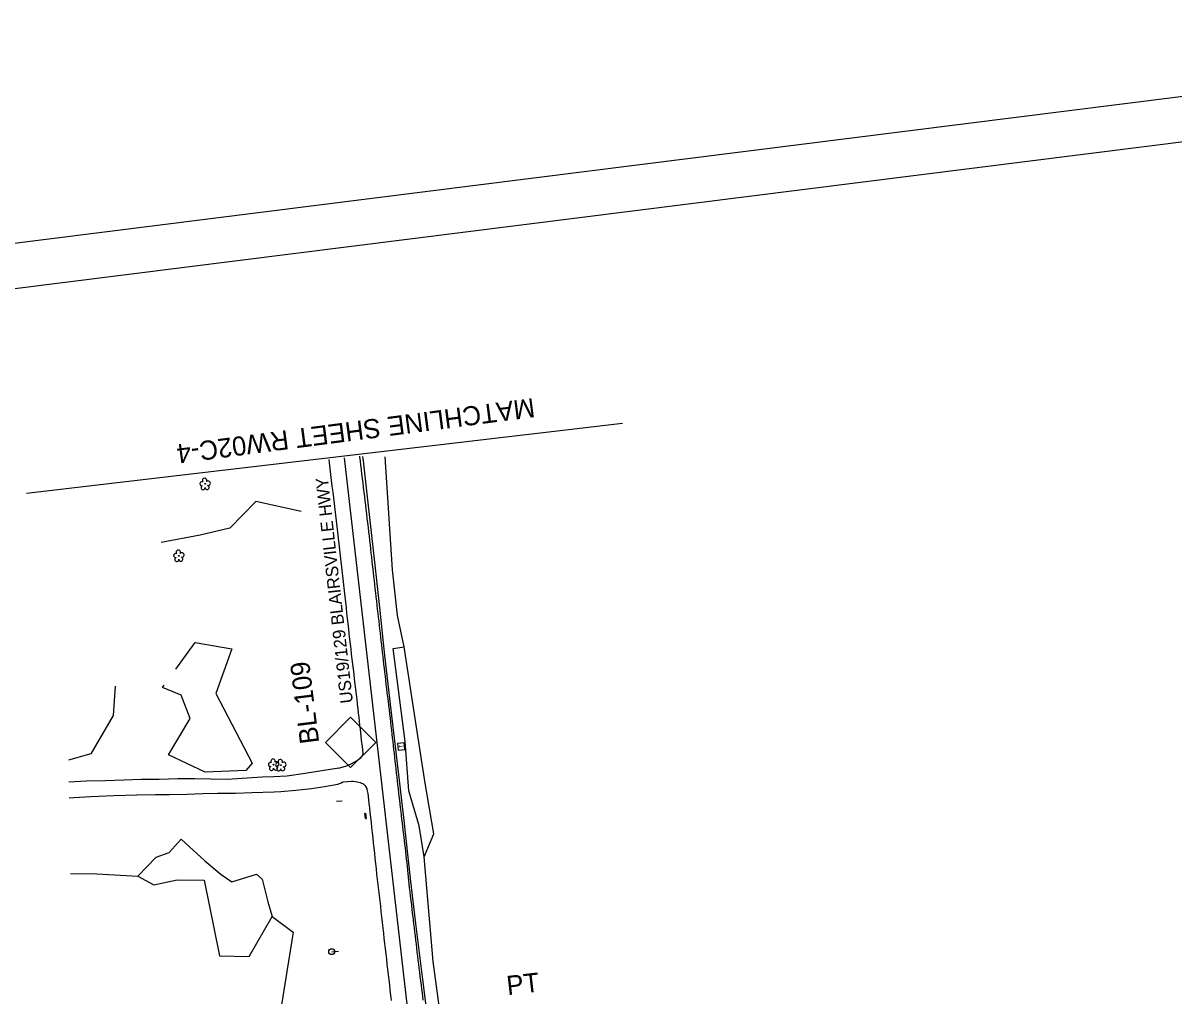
# Model space of a CAD drawing. Extents: x 477009 to 479892, y 492858 to 496862.
# Drawn here: x 477973 to 478933, y 496051 to 496862 of the extents above; entities that cross this region are included whole.
import ezdxf

# ---------------------------------------------------------------- set-up
doc = ezdxf.new("R2010")
doc.units = 0
for name, color, linetype in [('CTL Secondary Horizontal and Vertical CELL', 7, 'Continuous'), ('CTL Secondary Horizontal and Vertical Text', 7, 'Continuous'), ('CTL Sheet Border CELL', 7, 'Continuous'), ('Exist Guardrail', 7, 'Continuous'), ('Exist Horizontal Alignment', 7, 'Continuous'), ('Exist Other Culture Sign', 7, 'Continuous'), ('Exist Roads EOP', 7, 'Continuous'), ('Exist Roads EOP Text', 7, 'Continuous'), ('Exist Structure Minor Head and End Wall', 7, 'Continuous'), ('Exist Utilities Power Pole CELL', 7, 'Continuous'), ('Exist Utilities Telephone Pedestal CELL', 7, 'Continuous'), ('Exist Vegetation Hedge Row', 7, 'Continuous'), ('Exist Vegetation Tree CELL', 7, 'Continuous'), ('Exist Vegetation Woods Line', 7, 'Continuous'), ('Matchline', 7, 'Continuous'), ('Matchline Text', 7, 'Continuous'), ('Sheet Plot Border Outside CELL', 7, 'Continuous')]:
    doc.layers.add(name, color=color, linetype=linetype)

msp = doc.modelspace()

# ---------------------------------------------------------------- linework, layer by layer
at = {"layer": 'CTL Secondary Horizontal and Vertical CELL'}
msp.add_line((478246.12, 496262.13), (478246.12, 496262.13), dxfattribs=at)
msp.add_lwpolyline([(478225.26, 496262.2), (478246.23, 496283.17), (478267.23, 496262.17), (478246.26, 496241.2)], close=True, dxfattribs=at)
at = {"layer": 'CTL Sheet Border CELL'}
msp.add_lwpolyline([(477068.94, 496527.38), (477483.72, 493231.36), (479790.91, 493521.7), (479376.13, 496817.73)], close=True, dxfattribs=at)
at = {"layer": 'Exist Guardrail'}
for points in [[(478256.28, 496500.58), (478256.65, 496497), (478260.06, 496466.83), (478265.67, 496417.48), (478270.32, 496374.68), (478274.6, 496334.65), (478279.87, 496289.32), (478285.61, 496239.91), (478290.24, 496199.44), (478296.25, 496146.09)], [(478296.25, 496146.09), (478300.41, 496111.06), (478306.15, 496064.49), (478311.22, 496024.56), (478316.39, 495985.44), (478319.3, 495964.86), (478322.01, 495945.56)]]:
    msp.add_lwpolyline(points, dxfattribs=at)
at = {"layer": 'Exist Horizontal Alignment'}
msp.add_line((478294.37, 496036.52), (478241.07, 496499.45), dxfattribs=at)
at = {"layer": 'Exist Other Culture Sign'}
msp.add_line((478239.25, 496213.02), (478234.56, 496212.82), dxfattribs=at)
at = {"layer": 'Exist Roads EOP'}
for points in [[(478236.44, 496240.8), (478241.02, 496241.98), (478242.19, 496242.4), (478246.87, 496244.28), (478251.67, 496247.04), (478253.48, 496248.33), (478254.7, 496249.35), (478255.1, 496249.74), (478255.64, 496250.39), (478256.11, 496251.04), (478256.31, 496251.4), (478256.46, 496251.79), (478256.58, 496252.22), (478256.65, 496252.68), (478256.67, 496253.18), (478256.11, 496258.57), (478255.5, 496264), (478255.16, 496267), (478254.8, 496270.1), (478254.43, 496273.31), (478254.05, 496276.59), (478253.67, 496279.91), (478253.29, 496283.26), (478252.91, 496286.65), (478252.51, 496290.17), (478252.09, 496293.91), (478251.63, 496297.88), (478251.14, 496302.08), (478250.64, 496306.37), (478250.14, 496310.63), (478249.63, 496314.85), (478249.12, 496319.04), (478248.62, 496323.21), (478248.12, 496327.38), (478247.62, 496331.54), (478247.13, 496335.7), (478246.64, 496339.87), (478246.16, 496344.07), (478245.67, 496348.29), (478245.19, 496352.54), (478244.71, 496356.82), (478244.22, 496361.13), (478243.73, 496365.48), (478243.24, 496369.86), (478242.74, 496374.33), (478242.22, 496378.95), (478241.69, 496383.71), (478241.14, 496388.6), (478240.59, 496393.56), (478240.04, 496398.46), (478239.49, 496403.33), (478238.94, 496408.16), (478238.39, 496412.98), (478237.84, 496417.83), (478237.3, 496422.7), (478236.76, 496427.61), (478236.22, 496432.51), (478235.67, 496437.36), (478235.13, 496442.16), (478234.59, 496446.92), (478234.03, 496451.67), (478233.46, 496456.45), (478232.88, 496461.26), (478232.27, 496466.1), (478231.66, 496470.94), (478231.05, 496475.79), (478230.44, 496480.63), (478229.83, 496485.46), (478229.21, 496490.35), (478228.59, 496495.37), (478228.28, 496497.98)], [(478253.7, 496500.95), (478253.77, 496500.32), (478254.2, 496496.76), (478254.63, 496493.2), (478255.06, 496489.63), (478255.49, 496486.02), (478255.93, 496482.33), (478256.38, 496478.58), (478256.84, 496474.76), (478257.3, 496470.94), (478257.74, 496467.18), (478258.18, 496463.49), (478258.61, 496459.87), (478259.04, 496456.26), (478259.47, 496452.61), (478259.92, 496448.92), (478260.38, 496445.2), (478260.84, 496441.47), (478261.28, 496437.77), (478261.7, 496434.11), (478262.11, 496430.48), (478262.51, 496426.9), (478262.89, 496423.4), (478263.26, 496419.96), (478263.62, 496416.6), (478263.97, 496413.3), (478264.33, 496410.05), (478264.69, 496406.85), (478265.05, 496403.7), (478265.42, 496400.52), (478265.8, 496397.24), (478266.19, 496393.86), (478266.58, 496390.37), (478266.98, 496386.85), (478267.37, 496383.39), (478267.76, 496380), (478268.15, 496376.66), (478268.54, 496373.33), (478268.93, 496369.98), (478269.31, 496366.6), (478269.7, 496363.2), (478270.08, 496359.81), (478270.46, 496356.49), (478270.84, 496353.23), (478271.22, 496350.03), (478271.59, 496346.86), (478271.96, 496343.64), (478272.33, 496340.4), (478272.7, 496337.12), (478273.07, 496333.82), (478273.44, 496330.53), (478273.82, 496327.24), (478274.21, 496323.95), (478274.6, 496320.65), (478274.99, 496317.31), (478275.39, 496313.93), (478275.79, 496310.52), (478276.2, 496307.07), (478276.62, 496303.58), (478277.04, 496300.04), (478277.47, 496296.46), (478277.9, 496292.88), (478278.32, 496289.34), (478278.74, 496285.86), (478279.15, 496282.42), (478279.55, 496279.02), (478279.93, 496275.67), (478280.31, 496272.37), (478280.67, 496269.1), (478281.03, 496265.86), (478281.39, 496262.62), (478281.75, 496259.37), (478282.11, 496256.12), (478282.47, 496252.86), (478282.84, 496249.61), (478283.21, 496246.36), (478283.59, 496243.1), (478283.96, 496239.84), (478284.33, 496236.56), (478284.71, 496233.26), (478285.08, 496229.94), (478285.45, 496226.64), (478285.82, 496223.41), (478286.2, 496220.25), (478286.57, 496217.14), (478286.95, 496214.06), (478287.32, 496210.92), (478287.7, 496207.75), (478288.09, 496204.54), (478288.47, 496201.32), (478288.85, 496198.16), (478289.22, 496195.04), (478289.59, 496191.97), (478289.95, 496188.95), (478290.64, 496183.01), (478291.31, 496177.17), (478291.66, 496174.16), (478292.01, 496171.07), (478292.38, 496167.91), (478292.74, 496164.74), (478293.08, 496161.62), (478293.4, 496158.56), (478293.7, 496155.55), (478294.28, 496149.64), (478294.88, 496143.85), (478295.21, 496140.86), (478295.58, 496137.62), (478295.99, 496134.13), (478296.44, 496130.39), (478296.91, 496126.64), (478297.34, 496123.13), (478297.74, 496119.86), (478298.11, 496116.83), (478298.48, 496113.85), (478298.85, 496110.74), (478299.23, 496107.51), (478299.62, 496104.15), (478300.01, 496100.74), (478300.4, 496097.35), (478300.8, 496093.98), (478301.2, 496090.64), (478301.6, 496087.32), (478301.99, 496083.99), (478302.39, 496080.66), (478302.79, 496077.33), (478303.2, 496073.97), (478303.63, 496070.52), (478304.08, 496066.99), (478304.55, 496063.37), (478305.01, 496059.81), (478305.44, 496056.43), (478305.83, 496053.24), (478306.54, 496047.29)], [(478236.44, 496240.8), (478223.92, 496238.63), (478208.46, 496236.09), (478193.22, 496234.13), (478182.34, 496233.34), (478172.59, 496233.07), (478156, 496231.93), (478143.27, 496231.15), (478129.63, 496231.57), (478116.33, 496231.74), (478102.38, 496231.66), (478086.58, 496231.11), (478071.99, 496231.1), (478057.25, 496230.71), (478041.97, 496230.07), (478025.75, 496229.73), (478011.4, 496229.02)], [(478280.38, 496047.01), (478279.88, 496051.32), (478279.39, 496055.63), (478278.89, 496059.93), (478278.38, 496064.23), (478277.88, 496068.53), (478277.37, 496072.82), (478276.86, 496077.12), (478276.35, 496081.41), (478275.84, 496085.72), (478275.34, 496090.04), (478274.86, 496094.39), (478274.38, 496098.76), (478273.9, 496103.16), (478273.41, 496107.59), (478272.91, 496112.07), (478272.39, 496116.58), (478271.87, 496121.09), (478271.35, 496125.59), (478270.82, 496130.08), (478270.28, 496134.54), (478269.74, 496138.99), (478269.23, 496143.42), (478268.72, 496147.85), (478268.24, 496152.27), (478267.76, 496156.67), (478267.29, 496161.04), (478266.83, 496165.38), (478266.37, 496169.69), (478265.91, 496173.99), (478265.45, 496178.28), (478264.98, 496182.58), (478264.52, 496186.88), (478264.06, 496191.15), (478263.59, 496195.36), (478263.13, 496199.52), (478262.67, 496203.62), (478262.23, 496207.52), (478261.83, 496211.07), (478261.45, 496214.26), (478260.8, 496219.52), (478260.23, 496222.78), (478259.97, 496223.62), (478259.49, 496224.64), (478259.08, 496225.35), (478258.86, 496225.63), (478258.25, 496226.26), (478257.44, 496226.93), (478256.61, 496227.5), (478255.74, 496227.96), (478254.65, 496228.37), (478251.74, 496229.08), (478248.34, 496229.51), (478246.76, 496229.53), (478243.69, 496229.29), (478240.19, 496228.9), (478238.79, 496228.7)], [(478011.65, 496215.98), (478015.46, 496216.17), (478029.85, 496217.03), (478048.94, 496217.92), (478068.01, 496218.49), (478083.78, 496218.75), (478095.26, 496218.68), (478109.93, 496219.12), (478122.87, 496219.43), (478135.39, 496219.7), (478150.29, 496219.81), (478164.07, 496220.51), (478182.61, 496220.86), (478188.19, 496221.11), (478200.59, 496222.22), (478213.8, 496223.77), (478224.41, 496225.3), (478235.71, 496227.33), (478240.19, 496228.9)]]:
    msp.add_lwpolyline(points, dxfattribs=at)
at = {"layer": 'Exist Structure Minor Head and End Wall'}
for p, q in [((478258.16, 496203), (478258.99, 496203.1)), ((478258.66, 496198.6), (478258.16, 496203)), ((478259.48, 496198.7), (478258.99, 496203.1)), ((478258.66, 496198.6), (478259.48, 496198.7))]:
    msp.add_line(p, q, dxfattribs=at)
at = {"layer": 'Exist Utilities Power Pole CELL'}
for q in [(478236.14, 496088.04), (478230.53, 496087.63)]:
    msp.add_line((478230.53, 496087.63), q, dxfattribs=at)
msp.add_circle((478230.53, 496087.63), 2.45, dxfattribs=at)
at = {"layer": 'Exist Utilities Telephone Pedestal CELL'}
msp.add_line((478288.46, 496258.61), (478288.46, 496258.61), dxfattribs=at)
msp.add_lwpolyline([(478291.57, 496256.22), (478290.95, 496261.77), (478285.39, 496261.15), (478286.01, 496255.59), (478291.57, 496256.22)], dxfattribs=at)
at = {"layer": 'Exist Vegetation Hedge Row'}
for points in [[(478205.09, 496454.64), (478167.18, 496462.99), (478145.75, 496440.73), (478120.83, 496434.88), (478088.4, 496428.93)], [(478307.6, 496166.65), (478303.33, 496192.67), (478294.92, 496221.75), (478291.74, 496262.95), (478281.87, 496340.48), (478290.83, 496341.94)], [(478068.84, 496150.59), (478084.34, 496166.33), (478094.91, 496170.28), (478105.09, 496181.59), (478124.87, 496163.49), (478138.33, 496151.97), (478147.36, 496145.78), (478167.84, 496152.29), (478172.49, 496148.12), (478177.26, 496129.3), (478180.86, 496117.02)]]:
    msp.add_lwpolyline(points, dxfattribs=at)
at = {"layer": 'Exist Vegetation Tree CELL'}
for p, q in [((478124.98, 496477.67), (478124.98, 496477.67)), ((478103.08, 496417.76), (478103.08, 496417.76)), ((478182.08, 496243.59), (478182.08, 496243.59)), ((478188.05, 496243.15), (478188.05, 496243.15))]:
    msp.add_line(p, q, dxfattribs=at)
for centre in [(478124.98, 496477.67), (478103.08, 496417.76), (478182.08, 496243.59), (478188.05, 496243.15)]:
    msp.add_circle(centre, 0.326, dxfattribs=at)
for centre, radius, start, end in [((478122.37, 496477.83), 1.73, 62.66361, 279.3457), ((478124.59, 496480.55), 1.86, 330.16508, 219.71335), ((478127.53, 496478.26), 1.9, 257.1011, 134.19993), ((478123.27, 496474.55), 1.69, 111.56708, 6.23104), ((478126.65, 496474.77), 1.7, 181.28216, 74.55999), ((478102.7, 496420.63), 1.86, 330.16508, 219.71335), ((478100.47, 496417.91), 1.73, 62.66361, 279.3457), ((478101.38, 496414.64), 1.69, 111.56708, 6.23104), ((478104.75, 496414.86), 1.7, 181.28216, 74.55999), ((478105.63, 496418.35), 1.9, 257.1011, 134.19993), ((478179.47, 496243.74), 1.73, 62.66361, 279.3457), ((478180.37, 496240.47), 1.69, 111.56708, 6.23104), ((478181.69, 496246.46), 1.86, 330.16508, 219.71335), ((478183.75, 496240.69), 1.7, 181.28216, 74.55999), ((478184.62, 496244.18), 1.9, 257.1011, 134.19993), ((478185.44, 496243.31), 1.73, 62.66361, 279.3457), ((478186.34, 496240.03), 1.69, 111.56708, 6.23104), ((478187.66, 496246.03), 1.86, 330.16508, 219.71335), ((478189.72, 496240.25), 1.7, 181.28216, 74.55999), ((478190.6, 496243.74), 1.9, 257.1011, 134.19993)]:
    msp.add_arc(centre, radius, start, end, dxfattribs=at)
at = {"layer": 'Exist Vegetation Woods Line'}
for points in [[(478307.6, 496166.65), (478315.65, 496186.02), (478308.35, 496228.08), (478300.57, 496278.47), (478290.83, 496341.94), (478285.42, 496368.09), (478281.3, 496406), (478275.08, 496500.33)], [(478100.6, 496323.12), (478116.73, 496345.43), (478147.32, 496340.13), (478133.93, 496302.88), (478164.17, 496244.8), (478158.98, 496238.81), (478125.08, 496237.34), (478094.54, 496251.82), (478112.49, 496282.2), (478105.03, 496301.48), (478089.59, 496307.88)], [(478049.99, 496308.95), (478048.33, 496284.64), (478029.65, 496252.74), (478011.04, 496247.2)], [(478089.59, 496307.88), (478090.93, 496309.74)], [(478399.23, 495690.32), (478384.66, 495691.24), (478371.87, 495740.52), (478369.24, 495761.19), (478365.85, 495787.93), (478360.6, 495845.29), (478355.04, 495887.42), (478330.8, 495968.29), (478324.41, 496011.5), (478315.1, 496079.43), (478307.6, 496166.65)], [(478012.87, 496152.88), (478034.88, 496152.53), (478068.84, 496150.59), (478082.27, 496143.35), (478101.59, 496147.52), (478124.34, 496147.18)], [(478124.34, 496147.18), (478137.07, 496084.24), (478161.84, 496083.75), (478180.86, 496117.02)], [(478180.86, 496117.02), (478198.43, 496103.96), (478184.66, 496019.14), (478163.99, 496003.77), (478169.25, 495989.25), (478191.35, 496000.56)]]:
    msp.add_lwpolyline(points, dxfattribs=at)
at = {"layer": 'Matchline'}
msp.add_line((478472.84, 496527.98), (477976.24, 496469.75), dxfattribs=at)
at = {"layer": 'Sheet Plot Border Outside CELL'}
msp.add_lwpolyline([(479892.02, 493161.67), (479426.36, 496862.01), (477009.3, 496557.84), (477474.96, 492857.5)], close=True, dxfattribs=at)

# ---------------------------------------------------------------- texts
at = {"layer": 'CTL Secondary Horizontal and Vertical Text'}
msp.add_text('BL-109', height=16, rotation=97.12475, dxfattribs=at).set_placement((478220.16, 496261.96))
at = {"layer": 'Exist Horizontal Alignment'}
msp.add_text('PT', height=16, rotation=6.56846, dxfattribs=at).set_placement((478377.23, 496051.34))
at = {"layer": 'Exist Roads EOP Text'}
msp.add_text('US19/129 BLAIRSVILLE HWY', height=10.4, rotation=96.35832, dxfattribs=at).set_placement((478248.29, 496295.29))
at = {"layer": 'Exist Utilities Telephone Pedestal CELL'}
msp.add_text('T', height=3.42, rotation=96.42995, dxfattribs=at).set_placement((478290.29, 496257.67))
at = {"layer": 'Matchline Text'}
msp.add_text('MATCHLINE SHEET RW02C-4', height=16, rotation=187.44169, dxfattribs=at).set_placement((478398.69, 496549.43))

doc.saveas('drawing.dxf')
